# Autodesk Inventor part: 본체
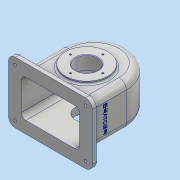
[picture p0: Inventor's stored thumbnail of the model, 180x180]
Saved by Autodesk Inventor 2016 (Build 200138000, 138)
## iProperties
Created: 2018-11
Part Number: 본체
Material: 알루미늄 6061
Document SubType Name: Modeling
Designer: user
Density: 2.7 g/cm^3
Appearance: 알루미늄 - 평지
Mass: 1092.08 g
Surface Area: 1182.21 cm^2
Volume: 404.475 cm^3
Author: user
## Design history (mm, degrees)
sketch "스케치1"
  geometry: L1 (-75, 55)-(75, 55); L2 (75, 55)-(75, -55); L3 (75, -55)-(-75, -55); L4 (-75, -55)-(-75, 55); L5 (-75, 55)-(75, -55); L6 (75, 55)-(-75, -55); 1 further point
  constraints: 12 end point, 2 midpoint, 2 parallel, 1 horizontal, 1 perpendicular
  dimensions: "d0" = 150 distance of L2.end L3.end; "d1" = 110 distance of L1.end L2.end
extrude "돌출1" new body sketch "스케치1" distance "d2" = 10; taper "d3" = 0 deg
node "작업 평면1"
sketch "스케치2"
  geometry: L1 (0, 10)-(150, 10) reference; L2 (133, 10)-(133, 78); L3 (17, 10)-(17, 78); L4 (150, 0)-(0, 0) reference; A1 r 58 centre (75, 78) between (133, 78) and (17, 78); 2 further points
  constraints: 4 end point, 2 horizontal alignment, 2 point on circle, 2 point on line, 2 vertical, 1 centre point, 1 midpoint, 1 vertical alignment
  dimensions: "d5" = 78 distance from line of L2.end L4; "d6" = 58 radius of A1
extrude "돌출2" join sketch "스케치2" distance "d7" = 77; taper "d8" = 0 deg
feature "쉘3" dims "d23" = 10, "d24" = 6, "d25" = 5
sketch "스케치3"
  geometry: L1 (-150, 10)-(0, 10) reference; L2 (0, 0)-(-150, 0) reference; C1 r 38 at (-75, 65); 2 further points
  constraints: 1 centre point, 1 midpoint, 1 vertical alignment
  dimensions: "d11" = 76 diameter of C1; "d12" = 65 distance from line of L2 C1.centre
extrude "돌출3" join sketch "스케치3" distance "d13" = 5; taper "d14" = 0 deg
sketch "스케치4"
  geometry: L1 (0, 10)-(150, 10) reference; L2 (150, 0)-(0, 0) reference; C1 r 38 at (75, 65); 2 further points
  constraints: 1 centre point, 1 midpoint, 1 vertical alignment
  dimensions: "d15" = 76 diameter of C1; "d16" = 65 distance from line of L2 C1.centre
extrude "돌출4" join sketch "스케치4" distance "d17" = 10; taper "d18" = 0 deg
sketch "스케치5"
  geometry: L1 (-75, -78)-(75, -78) reference; L2 (-58, -68)-(58, -68) reference; C1 r 28 at (0, -13); 2 further points
  constraints: 1 centre point, 1 midpoint, 1 vertical alignment
  dimensions: "d26" = 56 diameter of C1; "d27" = 65 distance from line of C1.centre L1
extrude "돌출5" join sketch "스케치5" distance "d28" = 14; taper "d29" = 0 deg
feature "면 기울기1" dims angle "d30" = 40 deg
sketch "스케치6"
  geometry: C1 r 20 at (0, 0); C2 r 38 at (0, 0) reference; 1 further point
  constraints: 1 centre point, 1 concentric
  dimensions: "d31" = 40 diameter of C1
extrude "돌출6" cut sketch "스케치6" stored distance "d32" = 14; taper "d33" = 0 deg
node "작업 평면2"
sketch "스케치7"
  geometry: L1 (38, 43.5)-(-38, 43.5) reference; L2 (75, 55)-(75, -55) reference; C1 r 6 at (0, 0); 1 further point
  constraints: 1 centre point
  dimensions: "d35" = 12 diameter of C1; "d36" = 43.5 distance from line of C1.centre L1; "d37" = 75 distance from line of C1.centre L2
extrude "돌출7" join sketch "스케치7" stored distance "d38" = 10; taper "d39" = 0 deg
sketch "스케치8"
  geometry: C1 r 6 at (0, 0) reference; 1 further point
hole "구멍1" sketch "스케치8" at (0, 0) diameter "d42" = 4.459; stored, may be unused: countersink angle "d46" = 90 deg, drill point angle "d48" = 118 deg; dims "d43" = 100, "d44" = 4, "d45" = 2, "d47" = 12.8
sketch "스케치9" dims "d49" = 58
  geometry: C1 r 38 at (0, 0) reference; 3 further points
  constraints: 2 horizontal alignment, 3 other
hole "구멍2" sketch "스케치9" at (-29, 0) diameter "d50" = 3.242; stored, may be unused: countersink angle "d54" = 90 deg, drill point angle "d56" = 118 deg; dims "d51" = 8, "d52" = 4, "d53" = 2, "d55" = 10
sketch "스케치10" dims "d60" = 58
  geometry: C1 r 20 at (0, 0) reference; 3 further points
  constraints: 2 horizontal alignment, 3 other
hole "구멍3" sketch "스케치10" at (-29, 0) diameter "d61" = 3.242; stored, may be unused: countersink angle "d65" = 90 deg, drill point angle "d67" = 118 deg; dims "d62" = 8, "d63" = 4, "d64" = 2, "d66" = 10
fillet "모깎기1" dims "d71" = 12
sketch "스케치11"
  geometry: A1 r 12 centre (-63, 43) between (-63, 55) and (-75, 43) reference; A2 r 12 centre (63, 43) between (75, 43) and (63, 55) reference; A3 r 12 centre (63, -43) between (63, -55) and (75, -43) reference; A4 r 12 centre (-63, -43) between (-75, -43) and (-63, -55) reference; 1 further point
hole "구멍4" sketch "스케치11" at (-63, -43), (63, -43), (63, 43), (-63, 43) diameter "d72" = 12; stored, may be unused: countersink angle "d76" = 90 deg, drill point angle "d78" = 0 deg; dims "d73" = 8, "d74" = 4, "d75" = 2, "d77" = 4
sketch "스케치12"
  geometry: C1 r 6 at (-63, 43) reference; C2 r 6 at (63, 43) reference; C3 r 6 at (-63, -43) reference; C4 r 6 at (63, -43) reference; 1 further point
hole "구멍5" sketch "스케치12" at (-63, 43), (-63, -43), (63, -43), (63, 43) diameter "d79" = 5; stored, may be unused: countersink angle "d83" = 90 deg, drill point angle "d85" = 0 deg; dims "d80" = 8, "d81" = 4, "d82" = 2, "d84" = 4
fillet "모깎기2" dims "d86" = 13
fillet "모깎기3" dims "d87" = 8
fillet "모깎기4" dims "d88" = 3
chamfer "모따기1" distance "d89" = 1; stored, may be unused: second distance "d90" = 2, angle "d91" = 45 deg
sketch "스케치13"
  geometry: L1 (68.5, -78)-(-17.5, -78) reference; L2 (-13, 0)-(-13, -65) reference; 2 further points
  constraints: 1 other
  dimensions: "d93" = 40 distance from line of L1 point (25.5, -38); "d94" = 38.5 distance from line of point (25.5, -38) L2
feature "엠보싱1" sketch "스케치13" dims "d0" = 150, "d1" = 110, "d95" = 0.5, "d96" = 0
feature "면 기울기3" dims angle "d97" = 5 deg
fillet "모깎기6" dims "d98" = 3
node "솔리드1"
pattern_circular "원형 패턴1" dims angle "d58" = 360 deg
pattern_circular "원형 패턴2" dims angle "d69" = 360 deg
node "투영된 루프1"
node "투영된 루프2"
node "투영된 루프3"
other parameters: "d4" = -93.5, "d34" = -142
